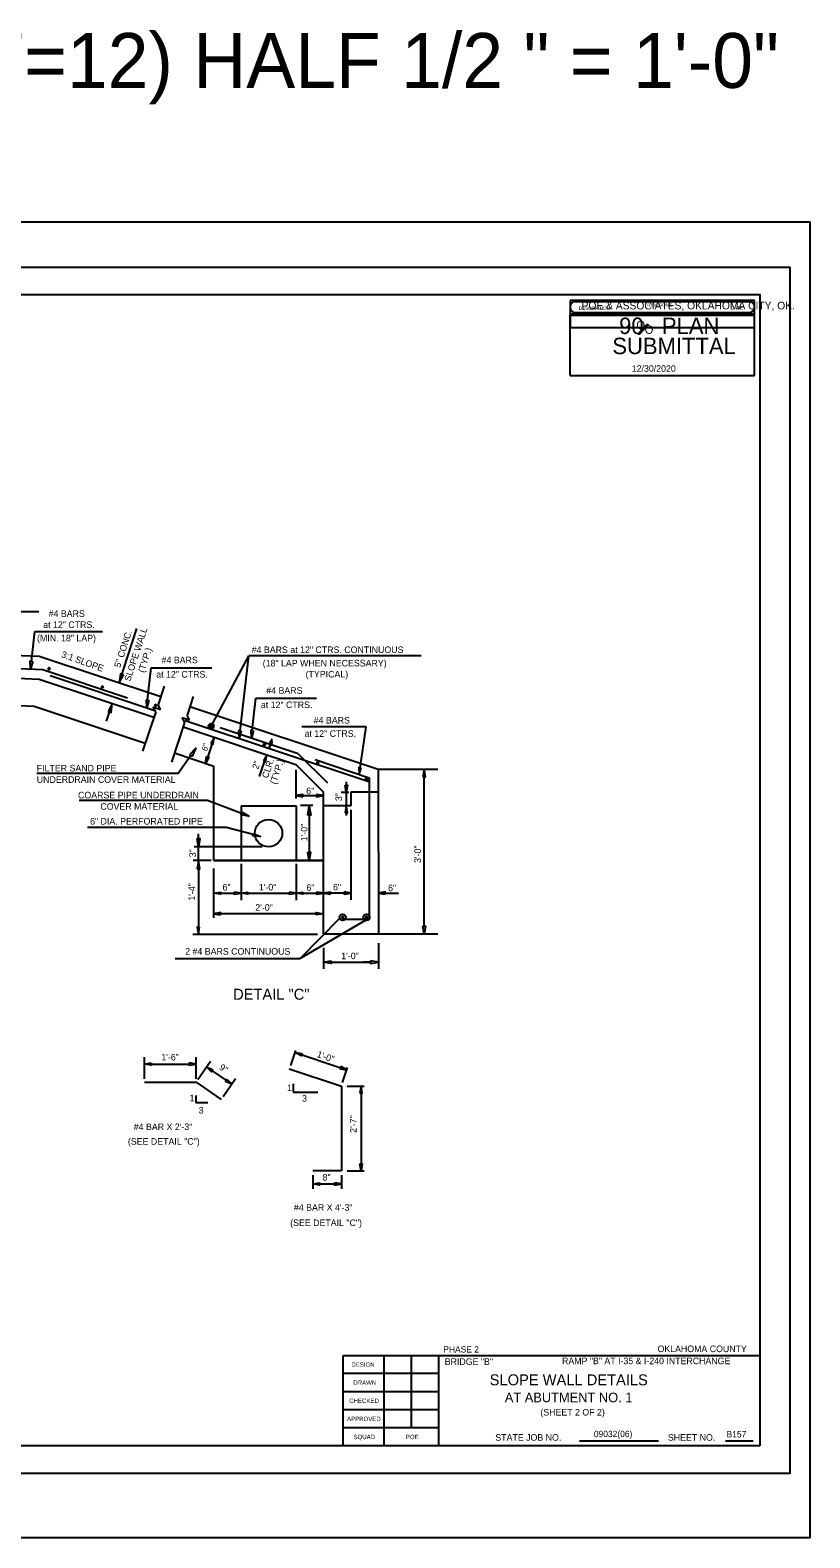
# Model space of a CAD drawing. Extents: x 570 to 2152770, y 726 to 139926.
# Drawn here: x 2151976.17 to 2151990.39, y 139311.06 to 139338.55 of the extents above; entities that cross this region are included whole.
import ezdxf

# ---------------------------------------------------------------- set-up
doc = ezdxf.new("R2010")
doc.units = 0
for name, color, linetype in [('4', 7, 'Continuous'), ('7', 7, 'Continuous'), ('9', 7, 'Continuous'), ('Default', 7, 'Continuous'), ('PR_Dimensions', 7, 'Continuous'), ('PR_Reinforcing', 7, 'Continuous'), ('PR_SlopeWall', 7, 'Continuous'), ('S', 7, 'Continuous'), ('SHT_Plot_Shape_Full', 7, 'Continuous'), ('SHT_Plot_Shape_Half', 7, 'Continuous'), ('SHT_Sheet_Border', 7, 'Continuous'), ('SHT_Stamp_90_Submit', 7, 'Continuous'), ('SHT_Stamp_Rev_Block', 7, 'Continuous'), ('SHT_Standard_Sheet_Lines', 7, 'Continuous'), ('SHT_Standard_Sheet_Txt', 7, 'Continuous'), ('T', 7, 'Continuous'), ('T-Subtitle', 7, 'Continuous'), ('T-Title', 7, 'Continuous'), ('WEEPHOLES', 7, 'Continuous')]:
    doc.layers.add(name, color=color, linetype=linetype)

# ---------------------------------------------------------------- blocks, each defined once
blk = doc.blocks.new('DWG01008_7')
at = {"layer": 'Default'}
for p, q in [((-0.0132, 0), (0, 0.0132)), ((0, 0.0132), (0, -0.0132)), ((0, -0.0132), (0.0132, 0))]:
    blk.add_line(p, q, dxfattribs=at)
blk = doc.blocks.new('ARROWHD_15')
at = {"layer": 'Default'}
blk.add_lwpolyline([(0.0261, -0.0045), (0.0261, 0.0043), (-0.0004, -0.0001)], close=True, dxfattribs=at)

msp = doc.modelspace()

# ---------------------------------------------------------------- linework, layer by layer
at = {"layer": '4'}
for p, q in [((2151982.522, 139324.658), (2151982.022, 139324.658)), ((2151982.022, 139324.658), (2151982.022, 139324.406)), ((2151982.022, 139324.406), (2151981.522, 139324.406)), ((2151980.895, 139319.612), (2151981.849, 139319.294)), ((2151981.849, 139319.294), (2151981.849, 139317.753)), ((2151981.849, 139317.753), (2151981.327, 139317.753))]:
    msp.add_line(p, q, dxfattribs=at)
msp.add_lwpolyline([(2151978.256, 139319.366), (2151979.198, 139319.366), (2151979.657, 139319.053)], dxfattribs=at)
at = {"layer": '7'}
for p, q in [((2151973.339, 139326.343), (2151976.248, 139326.223)), ((2151976.248, 139326.223), (2151978.271, 139325.548)), ((2151978.804, 139325.371), (2151979.521, 139325.132)), ((2151979.521, 139323.409), (2151979.521, 139325.132)), ((2151979.521, 139323.409), (2151981.521, 139323.409))]:
    msp.add_line(p, q, dxfattribs=at)
at = {"layer": '9'}
for start, end in [(159.6694, 339.6694), (339.6694, 159.6694)]:
    msp.add_arc((2151978.461, 139326.24), 0.0143, start, end, dxfattribs=at)
at = {"layer": 'Defpoints'}
for p, q in [((2151982.522, 139325.075), (2151983.609, 139325.075)), ((2151982.522, 139322.07), (2151983.609, 139322.07))]:
    msp.add_line(p, q, dxfattribs=at)
at = {"layer": 'PR_Dimensions'}
for p, q in [((2151976.329, 139327.946), (2151974.141, 139327.946)), ((2151976.26, 139327.584), (2151977.491, 139327.584)), ((2151977.796, 139326.651), (2151978.118, 139327.638)), ((2151983.304, 139327.145), (2151980.163, 139327.145)), ((2151978.382, 139326.924), (2151979.486, 139326.924)), ((2151978.618, 139326.59), (2151978.506, 139326.254)), ((2151979.147, 139326.399), (2151979.035, 139326.063)), ((2151980.291, 139326.368), (2151981.395, 139326.368)), ((2151977.564, 139325.948), (2151977.668, 139326.266)), ((2151978.462, 139326.12), (2151978.223, 139325.403)), ((2151978.99, 139325.929), (2151978.749, 139325.205)), ((2151982.298, 139325.847), (2151981.128, 139325.847)), ((2151982.17, 139324.978), (2151982.298, 139325.847)), ((2151979.529, 139325.656), (2151979.371, 139325.181)), ((2151980.537, 139325.478), (2151980.586, 139325.626)), ((2151980.355, 139324.941), (2151980.487, 139325.337)), ((2151981.018, 139325.062), (2151981.018, 139324.543)), ((2151982.561, 139325.075), (2151983.475, 139325.075)), ((2151983.355, 139322.21), (2151983.355, 139324.935)), ((2151981.845, 139324.659), (2151981.985, 139324.659)), ((2151981.938, 139324.845), (2151981.938, 139324.406)), ((2151979.409, 139324.506), (2151977.064, 139324.506)), ((2151981.083, 139324.594), (2151981.518, 139324.594)), ((2151981.325, 139324.41), (2151981.1, 139324.41)), ((2151981.938, 139324.406), (2151981.938, 139324.231)), ((2151982.021, 139324.333), (2151982.021, 139322.69)), ((2151979.75, 139324.014), (2151977.221, 139324.014)), ((2151979.242, 139323.409), (2151979.242, 139323.895)), ((2151980.405, 139323.659), (2151979.166, 139323.659)), ((2151979.475, 139323.409), (2151979.147, 139323.409)), ((2151979.471, 139323.409), (2151979.193, 139323.409)), ((2151979.242, 139323.409), (2151979.242, 139322.071)), ((2151979.518, 139323.264), (2151979.518, 139322.365)), ((2151981.521, 139323.409), (2151979.521, 139323.409)), ((2151980.019, 139323.346), (2151980.019, 139322.689)), ((2151981.021, 139323.346), (2151981.021, 139322.689)), ((2151979.643, 139322.814), (2151979.894, 139322.814)), ((2151980.144, 139322.814), (2151980.895, 139322.814)), ((2151981.146, 139322.814), (2151981.396, 139322.814)), ((2151982.021, 139322.815), (2151981.521, 139322.815)), ((2151982.521, 139322.815), (2151982.89, 139322.815)), ((2151981.521, 139322.44), (2151979.518, 139322.44)), ((2151982.291, 139322.32), (2151981.095, 139321.624)), ((2151979.139, 139322.065), (2151981.414, 139322.065)), ((2151982.522, 139321.904), (2151982.522, 139321.433)), ((2151982.642, 139322.07), (2151983.475, 139322.07)), ((2151978.818, 139321.624), (2151981.095, 139321.624)), ((2151981.522, 139321.818), (2151981.522, 139321.433)), ((2151981.662, 139321.553), (2151982.382, 139321.553)), ((2151982.382, 139321.553), (2151982.242, 139321.553)), ((2151980.926, 139319.673), (2151981.016, 139319.945)), ((2151978.256, 139319.429), (2151978.256, 139319.823)), ((2151978.381, 139319.697), (2151979.072, 139319.697)), ((2151979.198, 139319.429), (2151979.198, 139319.823)), ((2151979.233, 139319.418), (2151979.459, 139319.75)), ((2151981.004, 139319.907), (2151981.838, 139319.629)), ((2151979.492, 139319.576), (2151979.744, 139319.404)), ((2151979.692, 139319.105), (2151979.918, 139319.437)), ((2151981.87, 139319.359), (2151981.962, 139319.634)), ((2151979.191, 139319.125), (2151979.191, 139318.999)), ((2151980.97, 139319.334), (2151980.97, 139319.185)), ((2151980.97, 139319.185), (2151981.418, 139319.185)), ((2151981.955, 139319.294), (2151982.265, 139319.294)), ((2151982.207, 139319.294), (2151982.207, 139317.794)), ((2151979.191, 139318.999), (2151979.411, 139318.999)), ((2151981.955, 139317.753), (2151982.265, 139317.753)), ((2151981.327, 139317.674), (2151981.327, 139317.42)), ((2151981.327, 139317.511), (2151981.849, 139317.511)), ((2151981.849, 139317.674), (2151981.849, 139317.42))]:
    msp.add_line(p, q, dxfattribs=at)
for points in [[(2151976.198, 139327.042), (2151976.26, 139327.584)], [(2151979.498, 139325.901), (2151980.163, 139327.145)], [(2151980, 139325.775), (2151980.163, 139327.145)], [(2151978.315, 139326.337), (2151978.382, 139326.924)], [(2151980.224, 139325.781), (2151980.291, 139326.368)], [(2151979.104, 139325.326), (2151978.874, 139324.997), (2151976.296, 139324.997)], [(2151980.027, 139324.267), (2151979.409, 139324.506)], [(2151981.261, 139324.239), (2151981.261, 139323.409)], [(2151980.241, 139323.882), (2151979.75, 139324.014)], [(2151981.818, 139322.356), (2151981.095, 139321.624)]]:
    msp.add_lwpolyline(points, dxfattribs=at)
for points in [[(2151976.221, 139327.039), (2151976.182, 139326.903), (2151976.175, 139327.044)], [(2151978.338, 139326.334), (2151978.299, 139326.198), (2151978.292, 139326.34)], [(2151980.023, 139325.773), (2151979.983, 139325.636), (2151979.977, 139325.778)], [(2151980.247, 139325.778), (2151980.208, 139325.642), (2151980.201, 139325.784)], [(2151979.082, 139325.341), (2151979.196, 139325.457), (2151979.126, 139325.311)], [(2151979.47, 139325.544), (2151979.509, 139325.531), (2151979.529, 139325.656)], [(2151979.391, 139325.306), (2151979.43, 139325.293), (2151979.371, 139325.181)], [(2151983.332, 139324.935), (2151983.379, 139324.935), (2151983.355, 139325.075)], [(2151981.917, 139324.784), (2151981.959, 139324.784), (2151981.938, 139324.659)], [(2151981.234, 139324.239), (2151981.261, 139324.399), (2151981.288, 139324.239)], [(2151981.24, 139324.274), (2151981.282, 139324.274), (2151981.261, 139324.399)], [(2151981.917, 139324.281), (2151981.959, 139324.281), (2151981.938, 139324.406)], [(2151980.036, 139324.289), (2151980.158, 139324.217), (2151980.019, 139324.245)], [(2151979.217, 139323.809), (2151979.267, 139323.809), (2151979.242, 139323.659)], [(2151980.247, 139323.904), (2151980.376, 139323.845), (2151980.235, 139323.859)], [(2151981.236, 139323.559), (2151981.286, 139323.559), (2151981.261, 139323.409)], [(2151979.217, 139323.258), (2151979.267, 139323.258), (2151979.242, 139323.409)], [(2151979.643, 139322.835), (2151979.643, 139322.794), (2151979.518, 139322.814)], [(2151979.894, 139322.835), (2151979.894, 139322.794), (2151980.019, 139322.814)], [(2151980.144, 139322.835), (2151980.144, 139322.794), (2151980.019, 139322.814)], [(2151980.895, 139322.835), (2151980.895, 139322.794), (2151981.021, 139322.814)], [(2151981.146, 139322.835), (2151981.146, 139322.794), (2151981.021, 139322.814)], [(2151981.396, 139322.835), (2151981.396, 139322.794), (2151981.521, 139322.814)], [(2151979.263, 139322.196), (2151979.221, 139322.196), (2151979.242, 139322.071)], [(2151983.332, 139322.21), (2151983.379, 139322.21), (2151983.355, 139322.07)], [(2151981.662, 139321.577), (2151981.662, 139321.53), (2151981.522, 139321.553)], [(2151982.382, 139321.577), (2151982.382, 139321.53), (2151982.522, 139321.553)], [(2151978.381, 139319.718), (2151978.381, 139319.676), (2151978.256, 139319.697)], [(2151979.072, 139319.718), (2151979.072, 139319.676), (2151979.198, 139319.697)], [(2151981.13, 139319.888), (2151981.116, 139319.848), (2151981.004, 139319.907)], [(2151979.504, 139319.593), (2151979.481, 139319.558), (2151979.389, 139319.647)], [(2151979.756, 139319.422), (2151979.732, 139319.387), (2151979.848, 139319.334)], [(2151981.836, 139319.653), (2151981.823, 139319.613), (2151981.949, 139319.593)], [(2151982.186, 139319.169), (2151982.228, 139319.169), (2151982.207, 139319.294)], [(2151982.186, 139317.878), (2151982.228, 139317.878), (2151982.207, 139317.753)], [(2151981.452, 139317.532), (2151981.452, 139317.49), (2151981.327, 139317.511)], [(2151981.723, 139317.532), (2151981.723, 139317.49), (2151981.849, 139317.511)]]:
    msp.add_lwpolyline(points, close=True, dxfattribs=at)
for centre, radius in [((2151979.474, 139325.86), 0.0479), ((2151981.871, 139322.375), 0.0565), ((2151982.306, 139322.375), 0.0565)]:
    msp.add_circle(centre, radius, dxfattribs=at)
at = {"layer": 'PR_Reinforcing'}
for p, q in [((2151973.43, 139327.016), (2151976.403, 139326.894)), ((2151976.403, 139326.894), (2151977.949, 139326.378)), ((2151976.54, 139326.784), (2151978.447, 139326.148)), ((2151979.002, 139325.964), (2151982.348, 139324.848)), ((2151981.063, 139325.357), (2151979.64, 139325.831)), ((2151981.063, 139325.357), (2151981.593, 139324.827)), ((2151981.369, 139325.25), (2151982.355, 139324.917)), ((2151982.355, 139324.917), (2151982.355, 139322.333)), ((2151982.355, 139322.333), (2151981.855, 139322.333))]:
    msp.add_line(p, q, dxfattribs=at)
for centre in [(2151976.518, 139326.909), (2151977.489, 139326.574), (2151978.461, 139326.239), (2151979.474, 139325.86), (2151980.445, 139325.525), (2151981.417, 139325.191), (2151982.306, 139324.899), (2151981.871, 139322.375), (2151982.306, 139322.375)]:
    msp.add_circle(centre, 0.0143, dxfattribs=at)
for centre, start, end in [((2151976.518, 139326.909), 159.6694, 339.6694), ((2151976.518, 139326.909), 339.6694, 159.6694), ((2151977.489, 139326.574), 159.6694, 339.6694), ((2151977.489, 139326.574), 339.6694, 159.6694), ((2151979.473, 139325.86), 159.6694, 339.6694), ((2151979.473, 139325.86), 339.6694, 159.6694), ((2151980.445, 139325.525), 159.6694, 339.6694), ((2151980.445, 139325.525), 339.6694, 159.6694), ((2151981.417, 139325.191), 159.6694, 339.6694), ((2151981.417, 139325.191), 339.6694, 159.6694), ((2151982.307, 139324.899), 159.6694, 339.6694), ((2151982.307, 139324.899), 339.6694, 159.6694), ((2151981.871, 139322.375), 1.9719, 181.9719), ((2151981.871, 139322.375), 181.9719, 1.9719), ((2151982.306, 139322.375), 1.9719, 181.9719), ((2151982.306, 139322.375), 181.9719, 1.9719)]:
    msp.add_arc(centre, 0.0143, start, end, dxfattribs=at)
at = {"layer": 'PR_SlopeWall'}
for p, q in [((2151973.339, 139327.261), (2151976.339, 139327.136)), ((2151973.339, 139327.261), (2151976.339, 139327.136)), ((2151976.339, 139327.136), (2151978.554, 139326.398)), ((2151973.326, 139326.844), (2151976.339, 139326.719)), ((2151973.339, 139326.844), (2151976.339, 139326.719)), ((2151976.339, 139326.719), (2151978.429, 139326.023)), ((2151976.339, 139326.719), (2151978.429, 139326.023)), ((2151979.087, 139326.22), (2151982.521, 139325.075)), ((2151978.962, 139325.845), (2151981.018, 139325.16)), ((2151981.018, 139325.16), (2151981.521, 139324.659)), ((2151982.521, 139325.075), (2151982.522, 139322.068)), ((2151981.522, 139322.07), (2151981.521, 139324.659)), ((2151981.522, 139322.07), (2151982.522, 139322.07))]:
    msp.add_line(p, q, dxfattribs=at)
at = {"layer": 'SHT_Plot_Shape_Full'}
msp.add_lwpolyline([(2151954.391, 139335.057), (2151990.391, 139335.057), (2151990.391, 139311.057), (2151954.391, 139311.057)], close=True, dxfattribs=at)
at = {"layer": 'SHT_Plot_Shape_Half'}
msp.add_lwpolyline([(2151956.028, 139334.232), (2151990.028, 139334.232), (2151990.028, 139312.232), (2151956.028, 139312.232)], close=True, dxfattribs=at)
at = {"layer": 'SHT_Sheet_Border'}
for p, q in [((2151981.878, 139312.732), (2151981.878, 139314.382)), ((2151981.878, 139314.382), (2151989.478, 139314.382)), ((2151983.628, 139312.732), (2151983.628, 139314.383))]:
    msp.add_line(p, q, dxfattribs=at)
msp.add_lwpolyline([(2151989.478, 139312.732), (2151957.978, 139312.732), (2151957.978, 139333.732), (2151989.478, 139333.732)], close=True, dxfattribs=at)
at = {"layer": 'SHT_Stamp_90_Submit'}
for p, q in [((2151986.118, 139333.603), (2151989.284, 139333.603)), ((2151986.018, 139333.353), (2151989.384, 139333.353)), ((2151986.018, 139332.254), (2151986.018, 139333.353)), ((2151986.118, 139333.403), (2151989.284, 139333.403)), ((2151987.261, 139333.015), (2151987.416, 139333.187)), ((2151987.279, 139333.015), (2151987.434, 139333.187)), ((2151987.284, 139333.015), (2151987.439, 139333.187)), ((2151987.292, 139333.015), (2151987.447, 139333.187)), ((2151987.416, 139333.187), (2151987.447, 139333.187)), ((2151989.384, 139332.254), (2151989.384, 139333.353)), ((2151987.261, 139333.015), (2151987.292, 139333.015)), ((2151986.018, 139332.254), (2151989.384, 139332.254))]:
    msp.add_line(p, q, dxfattribs=at)
for centre, start, end in [((2151986.118, 139333.503), 89.9952, 270), ((2151989.284, 139333.503), 270, 90.0048)]:
    msp.add_arc(centre, 0.1, start, end, dxfattribs=at)
at = {"layer": 'SHT_Stamp_Rev_Block'}
for p, q in [((2151986.018, 139333.624), (2151986.018, 139333.124)), ((2151989.384, 139333.624), (2151986.018, 139333.624)), ((2151989.384, 139333.124), (2151989.384, 139333.624)), ((2151989.384, 139333.374), (2151986.018, 139333.374)), ((2151989.384, 139333.124), (2151986.018, 139333.124))]:
    msp.add_line(p, q, dxfattribs=at)
at = {"layer": 'SHT_Standard_Sheet_Lines'}
for p, q in [((2151982.628, 139312.732), (2151982.628, 139314.383)), ((2151983.128, 139313.062), (2151983.128, 139314.383)), ((2151986.189, 139312.828), (2151987.629, 139312.828)), ((2151988.854, 139312.828), (2151989.356, 139312.828))]:
    msp.add_line(p, q, dxfattribs=at)
for points in [[(2151983.628, 139314.052), (2151981.878, 139314.052)], [(2151983.628, 139313.722), (2151981.878, 139313.722)], [(2151983.628, 139313.392), (2151981.878, 139313.392)], [(2151983.628, 139313.062), (2151981.878, 139313.062)]]:
    msp.add_lwpolyline(points, dxfattribs=at)
at = {"layer": 'T'}
msp.add_circle((2151980.521, 139323.908), 0.25, dxfattribs=at)
at = {"layer": 'WEEPHOLES'}
for p, q in [((2151980.021, 139324.408), (2151980.021, 139323.409)), ((2151980.021, 139324.408), (2151981.021, 139324.408)), ((2151981.021, 139324.408), (2151981.021, 139323.409)), ((2151980.021, 139323.409), (2151981.021, 139323.409))]:
    msp.add_line(p, q, dxfattribs=at)

# ---------------------------------------------------------------- block references
at = {"layer": 'PR_Dimensions'}
for name, p, xscale, yscale, rotation in [('ARROWHD_15', (2151977.796, 139326.653), 6.151530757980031, 6.151530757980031, 71.85226335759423), ('ARROWHD_15', (2151977.67, 139326.273), 6.151530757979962, 6.151530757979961, -106.5417947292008), ('DWG01008_7', (2151978.484, 139326.187), 5.344315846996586, 5.344315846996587, 71.56518708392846), ('DWG01008_7', (2151979.013, 139325.996), 5.344315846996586, 5.344315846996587, 71.56518708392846), ('ARROWHD_15', (2151980.53, 139325.458), 4.724399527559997, 4.724399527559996, 71.25269404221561), ('ARROWHD_15', (2151980.486, 139325.335), 4.724399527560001, 4.72439952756, -108.77447516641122), ('ARROWHD_15', (2151982.17, 139324.98), 4.724399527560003, 4.724399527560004, 81.62001236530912), ('ARROWHD_15', (2151981.52, 139324.594), 4.7243995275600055, 4.7243995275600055, 180), ('ARROWHD_15', (2151982.02, 139322.815), 4.7243995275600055, 4.7243995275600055, 180), ('ARROWHD_15', (2151981.513, 139322.44), 4.731946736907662, -4.731946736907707, 180)]:
    msp.add_blockref(name, p, dxfattribs=dict(at, xscale=xscale, yscale=yscale, rotation=rotation))
for p, xscale, yscale in [((2151981.021, 139324.594), 4.7243995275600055, 4.7243995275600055), ((2151981.525, 139322.815), 4.7243995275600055, 4.7243995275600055), ((2151982.526, 139322.816), 4.7243995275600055, 4.7243995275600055), ((2151979.518, 139322.44), 4.731946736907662, 4.731946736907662)]:
    msp.add_blockref('ARROWHD_15', p, dxfattribs=dict(at, xscale=xscale, yscale=yscale))

# ---------------------------------------------------------------- texts
at = {"layer": 'S'}
msp.add_text('SCALE:  FULL 1" = 1\'-0" (SF=12) HALF 1/2 " = 1\'-0"', height=1.00003, dxfattribs=at).set_placement((2151958.99, 139337.5))
at = {"layer": 'SHT_Stamp_90_Submit'}
for s, height, p in [('POE & ASSOCIATES, OKLAHOMA CITY, OK.', 0.14, (2151986.228, 139333.46)), ('90   PLAN', 0.3, (2151986.913, 139333.011)), ('O', 0.153, (2151987.227, 139333.1)), ('O', 0.153, (2151987.379, 139333.015)), ('SUBMITTAL', 0.3, (2151986.789, 139332.644)), ('12/30/2020', 0.12, (2151987.143, 139332.322))]:
    msp.add_text(s, height=height, dxfattribs=at).set_placement(p)
at = {"layer": 'SHT_Stamp_Rev_Block'}
for s, p in [('DESCRIPTION', (2151986.177, 139333.452)), ('REVISIONS', (2151987.426, 139333.511)), ('DATE', (2151988.947, 139333.456))]:
    msp.add_text(s, height=0.06, dxfattribs=at).set_placement(p)
at = {"layer": 'SHT_Standard_Sheet_Txt'}
for s, height, p in [('DESIGN', 0.08, (2151982.03, 139314.178)), ('DRAWN', 0.08, (2151982.066, 139313.848)), ('CHECKED', 0.08, (2151981.991, 139313.517)), ('APPROVED', 0.08, (2151981.952, 139313.187)), ('SQUAD', 0.08, (2151982.07, 139312.857)), ('POE', 0.08, (2151983.023, 139312.857)), ('STATE JOB NO.', 0.12, (2151984.655, 139312.828)), ('SHEET NO. ', 0.12, (2151987.802, 139312.828))]:
    msp.add_text(s, height=height, dxfattribs=at).set_placement(p)
at = {"layer": 'T'}
for s, height, p in [('#4 BARS', 0.12, (2151976.509, 139327.851)), ('at 12" CTRS.', 0.12, (2151976.411, 139327.65)), ('(MIN. 18" LAP)', 0.12, (2151976.299, 139327.406)), ('#4 BARS', 0.12, (2151978.569, 139327.006)), ('#4 BARS at 12" CTRS. CONTINUOUS', 0.12, (2151980.212, 139327.193)), ('at 12" CTRS.', 0.12, (2151978.472, 139326.745)), ('(18" LAP WHEN NECESSARY)', 0.12, (2151980.414, 139326.949)), ('(TYPICAL)', 0.12, (2151981.196, 139326.748)), ('#4 BARS', 0.12, (2151980.478, 139326.45)), ('at 12" CTRS.', 0.12, (2151980.38, 139326.189)), ('#4 BARS', 0.12, (2151981.343, 139325.908)), ('at 12" CTRS.', 0.12, (2151981.176, 139325.665)), ('UNDERDRAIN COVER MATERIAL', 0.12, (2151976.293, 139324.826)), ('FILTER SAND PIPE', 0.12, (2151976.293, 139325.034)), ('COARSE PIPE UNDERDRAIN', 0.12, (2151977.046, 139324.543)), ('6"', 0.12, (2151981.207, 139324.619)), ('COVER MATERIAL', 0.12, (2151977.453, 139324.336)), ('6" DIA. PERFORATED PIPE', 0.12, (2151977.266, 139324.065)), ('6"', 0.12, (2151979.681, 139322.862)), ('1\'-0"', 0.12, (2151980.343, 139322.864)), ('6"', 0.12, (2151981.21, 139322.856)), ('6"', 0.12, (2151981.696, 139322.864)), ('6"', 0.12, (2151982.7, 139322.849)), ('2\'-0"', 0.12, (2151980.278, 139322.493)), ('2 #4 BARS CONTINUOUS', 0.12, (2151979, 139321.692)), ('1\'-0"', 0.12, (2151981.846, 139321.61)), ('1\'-6"', 0.12, (2151978.565, 139319.763)), ('1', 0.12, (2151979.08, 139319.019)), ('1', 0.12, (2151980.859, 139319.204)), ('3', 0.12, (2151981.13, 139319.011)), ('3', 0.12, (2151979.246, 139318.796)), ('#4 BAR X 2\'-3"', 0.12, (2151978.062, 139318.493)), ('(SEE DETAIL "C")', 0.12, (2151977.955, 139318.226)), ('8"', 0.12, (2151981.505, 139317.573)), ('#4 BAR X 4\'-3"', 0.12, (2151980.982, 139317.022)), ('(SEE DETAIL "C")', 0.12, (2151980.914, 139316.743)), ('PHASE 2', 0.1152, (2151983.706, 139314.437)), ('OKLAHOMA COUNTY', 0.11979, (2151987.613, 139314.444)), ('BRIDGE "B" ', 0.12, (2151983.733, 139314.21)), ('RAMP "B" AT I-35 & I-240 INTERCHANGE', 0.11979, (2151985.872, 139314.224)), ('(SHEET 2 OF 2)', 0.11979, (2151985.477, 139313.288)), ('09032(06)', 0.1152, (2151986.452, 139312.894)), ('B157', 0.1152, (2151988.872, 139312.888))]:
    msp.add_text(s, height=height, dxfattribs=at).set_placement(p)
for s, height, rotation, p in [('5" CONC. ', 0.12, 71.9826, (2151977.815, 139326.917)), ('SLOPE WALL', 0.12, 71.9826, (2151977.999, 139326.667)), ('3:1 SLOPE', 0.12, 340.4558, (2151976.73, 139327.12)), ('(TYP.)', 0.12, 71.9826, (2151978.251, 139326.826)), ('6"', 0.1102, 70.4717, (2151979.395, 139325.394)), ('2"', 0.12, 71.6994, (2151980.331, 139325.063)), ('CLR.', 0.12, 71.6994, (2151980.508, 139324.9)), ('(TYP.)', 0.12, 71.6994, (2151980.655, 139324.791)), ('3"', 0.12, 90, (2151981.86, 139324.493)), ('1\'-0"', 0.12, 90, (2151981.229, 139323.76)), ('3"', 0.12, 90, (2151979.196, 139323.469)), ('3\'-0"', 0.12, 90, (2151983.299, 139323.365)), ('1\'-4"', 0.12, 90, (2151979.18, 139322.677)), ('9"', 0.12, 325.7113, (2151979.607, 139319.609)), ('1\'-0"', 0.12, 340.8033, (2151981.391, 139319.828)), ('2\'-7"', 0.12, 90, (2151982.124, 139318.443))]:
    msp.add_text(s, height=height, rotation=rotation, dxfattribs=at).set_placement(p)
at = {"layer": 'T-Subtitle'}
msp.add_text('AT ABUTMENT NO. 1', height=0.175, dxfattribs=at).set_placement((2151984.828, 139313.53))
at = {"layer": 'T-Title'}
for s, p in [('DETAIL "C"', (2151979.873, 139320.871)), ('SLOPE WALL DETAILS', (2151984.553, 139313.839))]:
    msp.add_text(s, height=0.2, dxfattribs=at).set_placement(p)

doc.saveas('drawing.dxf')
